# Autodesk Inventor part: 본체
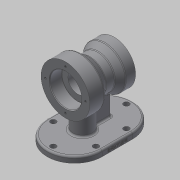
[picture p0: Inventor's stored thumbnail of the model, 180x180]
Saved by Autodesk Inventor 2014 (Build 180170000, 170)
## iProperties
Created: 2020-01
Part Number: 본체
Material: Generic
Document SubType Name: Modeling
Designer: kh
Density: 1 g/cm^3
Appearance: Default
Author: kh
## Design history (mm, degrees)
sketch "스케치1"
  geometry: L1 (-40, 0)-(-40, 40); L2 (40, 35)-(40, 0); L3 (-40, 0)-(40, 0); L4 (-16, 40)-(-1.103, 27.5); L5 (-1.103, 27.5)-(13.289, 27.5); L6 (13.289, 27.5)-(24, 35); L7 (-40, 40)-(-16, 40); L8 (24, 35)-(40, 35); 2 further points
  constraints: 16 end point, 5 perpendicular, 2 coincident, 1 midpoint, 1 parallel, 1 vertical
  dimensions: "d0" = 70 diameter of L8 L3; "d1" = 80 diameter of L7 L3; "d2" = 80 distance between parallel lines of L2 L1; "d3" = 24 distance of L1.end L4.start; "d4" = 16 distance of L6.end L2.start; "d5" = 55 diameter of L5 L3; "d6" = 40 deg angle of L5 L4; "d7" = 35 deg angle of L5 L6
revolve "회전1" sketch "스케치1" stored, may be unused: angle "d8" = 90 deg
sketch "스케치2"
  geometry: L1 (40, 0)-(-40, 0); L2 (40, 26)-(20, 26); L3 (20, 26)-(20, 16); L4 (20, 16)-(-23, 16); L5 (-23, 16)-(-23, 20); L6 (-23, 20)-(-40, 20); L7 (-40, 35)-(-40, -35) reference; L8 (40, 40)-(40, -40) reference; L9 (-40, 20)-(-40, 0); L10 (40, 26)-(40, 0); 1 further point
  constraints: 16 end point, 4 parallel, 2 midpoint, 2 point on line, 1 horizontal, 1 perpendicular
  dimensions: "d9" = 20 distance between parallel lines of L3 L8; "d10" = 17 distance between parallel lines of L7 L5; "d11" = 32 diameter of L4 L1; "d12" = 40 diameter of L6 L1; "d13" = 52 diameter of L2 L1
revolve "회전2" sketch "스케치2" stored, may be unused: angle "d14" = 90 deg
sketch "스케치3"
  geometry: L1 (-27.5, 0)-(27.5, 0); C1 r 20 at (0, 0) reference; 1 further point
  constraints: 2 coincident, 2 end point, 1 horizontal, 1 midpoint
  dimensions: "d15" = 55 distance of L1.end L1.start
hole "구멍1" sketch "스케치3" at (-27.5, 0), (27.5, 0) diameter "d16" = 3.242; stored, may be unused: countersink angle "d20" = 90 deg, drill point angle "d22" = 118 deg; dims "d17" = 9, "d18" = 4, "d19" = 2, "d21" = 11
sketch "스케치4"
  geometry: L1 (33, 0)-(-33, 0); C1 r 26 at (0, 0) reference; 1 further point
  constraints: 2 coincident, 2 end point, 1 horizontal, 1 midpoint
  dimensions: "d26" = 66 distance of L1.end L1.start
hole "구멍2" sketch "스케치4" at (33, 0), (-33, 0) diameter "d27" = 3.242; stored, may be unused: countersink angle "d31" = 90 deg, drill point angle "d33" = 118 deg; dims "d28" = 9, "d29" = 4, "d30" = 2, "d32" = 11
node "작업 평면1"
sketch "스케치7"
  geometry: L1 (-25, 0)-(25, 0); L2 (-25, -45)-(25, -45); L3 (25, 45)-(-25, 45); L4 (-25, 0)-(25, 0); A1 r 45 centre (-25, 0) between (-25, 45) and (-25, -45); A2 r 45 centre (25, 0) between (25, -45) and (25, 45); 3 further points
  constraints: 12 end point, 4 point on circle, 4 tangent, 2 centre point, 2 equal length, 2 midpoint, 1 coincident, 1 horizontal
  dimensions: "d38" = 50 distance of L1.end L1.start; "d39" = 45 radius of A1
extrude "돌출1" join sketch "스케치7" distance "d47" = 10; taper "d48" = 0 deg
sketch "스케치8"
  geometry: L1 (-25, -45)-(25, -45) reference; L2 (-25, 0)-(25, 0); L3 (-25, -35)-(25, -35); L4 (25, 35)-(-25, 35); C1 r 4.5 at (-25, 35); C2 r 4.5 at (25, 35); C3 r 4.5 at (-60, 0); C4 r 4.5 at (60, 0); C5 r 4.5 at (25, -35); C6 r 4.5 at (-25, -35); A1 r 45 centre (25, 0) between (25, -45) and (25, 45) reference; A2 r 45 centre (-25, 0) between (-25, 45) and (-25, -45) reference; A3 r 35 centre (-25, 0) between (-25, 35) and (-25, -35); A4 r 35 centre (25, 0) between (25, -35) and (25, 35); 2 further points
  constraints: 8 centre point, 8 end point, 6 point on circle, 5 coincident, 4 tangent, 2 parallel, 1 midpoint
  dimensions: "d49" = 10 distance between parallel lines of L1 L3; "d50" = 50 distance of L2.end A2.centre (derived); "d51" = 9 diameter of C1; "d52" = 9 diameter of C2; "d53" = 9 diameter of C3; "d54" = 9 diameter of C4; "d55" = 9 diameter of C5; "d56" = 9 diameter of C6
extrude "돌출2" cut sketch "스케치8" stored distance "d57" = 10; taper "d58" = 0 deg
sketch "스케치11"
  geometry: L1 (25, 45)-(-25, 45) reference; L2 (-70, 0)-(-70, -47.123); C1 r 16 at (-12, 0); A1 r 45 centre (-25, 0) between (-25, 45) and (-25, -45) reference; 1 further point
  constraints: 2 end point, 1 centre point, 1 perpendicular, 1 point on circle, 1 tangent
  dimensions: "d60" = 58 horizontal distance of C1.centre L2.end; "d62" = 16 radius of C1
extrude "돌출3" join sketch "스케치11" stored distance "d63" = 10; taper "d64" = 0 deg
sketch "스케치12"
  geometry: L1 (-30, -35)-(-30, -70); L2 (-25, -70)-(-70, -70) reference; L3 (-25, -70)-(25, -70) reference; L4 (-24, -35)-(-40, -35) reference; 1 further point
  constraints: 2 end point, 2 point on line, 1 vertical
  dimensions: "d65" = 10 distance from line of L4.end L1
feature "리브1" sketch "스케치12" dims "d66" = 1, "d67" = 10, "d68" = 0, "d69" = 0, "d70" = 1, "d71" = 1
sketch "스케치13"
  geometry: L1 (0, 0)-(50, 0) reference; L2 (0, 10)-(0, 10) reference; L3 (0, 0)-(0, 10) reference; L4 (0, 0)-(0, 0) reference; L5 (0, 0)-(0, 10) reference; L6 (-45, 0)-(-45, 10) reference; 2 further points
  constraints: 1 other
  dimensions: "d72" = 70 distance from line of point (25, 4) L6; "d73" = 4 distance from line of L1 point (25, 4)
feature "엠보싱1" sketch "스케치13" dims "d0" = 70, "d1" = 80, "d2" = 80, "d3" = 24, "d4" = 16, "d5" = 55, "d6" = 40 deg, "d7" = 35 deg, "d13" = 52, "d74" = 0.5, "d75" = 0
fillet "모깎기1" dims "d76" = 3
fillet "모깎기2" dims "d77" = 3
fillet "모깎기3" dims "d78" = 3
fillet "모깎기4" dims "d79" = 0.3
chamfer "모따기1" distance "d80" = 1; stored, may be unused: second distance "d81" = 2, angle "d82" = 45 deg
fillet "모깎기5" dims "d83" = 3
node "솔리드1"
pattern_circular "원형 패턴1" dims angle "d24" = 360 deg
pattern_circular "원형 패턴2" dims angle "d35" = 360 deg
node "투영된 루프1"
